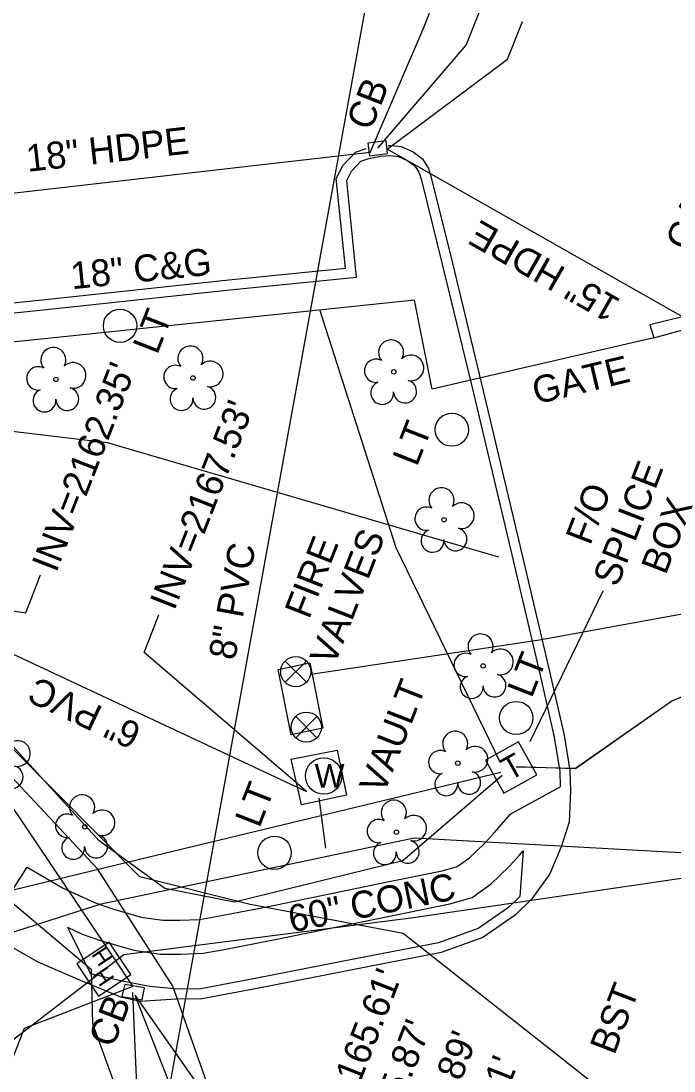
# Model space of a CAD drawing. Extents: x 945964 to 948456, y 631061 to 636061.
# Drawn here: x 946440.9 to 946537.5, y 633475.6 to 633631 of the extents above; entities that cross this region are included whole.
import ezdxf

# ---------------------------------------------------------------- set-up
doc = ezdxf.new("R2010")
doc.units = 0
for name, color, linetype in [('Exist Building', 7, 'Continuous'), ('Exist Building Text', 7, 'Continuous'), ('Exist Other Culture Fence Line', 7, 'Continuous'), ('Exist Other Culture Gate', 7, 'Continuous'), ('Exist Other Culture Gate Text', 7, 'Continuous'), ('Exist Roads Curbs', 7, 'Continuous'), ('Exist Roads Curbs Text', 7, 'Continuous'), ('Exist Roads EOP', 7, 'Continuous'), ('Exist Roads EOP Other', 7, 'Continuous'), ('Exist Roads EOP Other Text', 7, 'Continuous'), ('Exist Structure Minor Catch Basin', 7, 'Continuous'), ('Exist Structure Minor Catch Basin Text', 7, 'Continuous'), ('Exist Structure Minor Catch Basin Top Elevation', 7, 'Continuous'), ('Exist Structure Minor Pipes HDPE 15 Inch', 7, 'Continuous'), ('Exist Structure Minor Pipes HDPE 15 Inch Invert', 7, 'Continuous'), ('Exist Structure Minor Pipes HDPE 15 Inch Text', 7, 'Continuous'), ('Exist Structure Minor Pipes HDPE 18 Inch', 7, 'Continuous'), ('Exist Structure Minor Pipes HDPE 18 Inch Invert', 7, 'Continuous'), ('Exist Structure Minor Pipes HDPE 18 Inch Text', 7, 'Continuous'), ('Exist Structure Minor Pipes HDPE 8 Inch', 7, 'Continuous'), ('Exist Structure Minor Pipes HDPE 8 Inch Invert', 7, 'Continuous'), ('Exist Structure Minor Pipes HDPE 8 Inch Text', 7, 'Continuous'), ('Exist Structure Minor Pipes RCP 15 Inch Invert', 7, 'Continuous'), ('Exist Structure Minor Pipes RCP 18 Inch', 7, 'Continuous'), ('Exist Structure Minor Pipes RCP 18 Inch Invert', 7, 'Continuous'), ('Exist Utilities Gas UG Line SUE', 7, 'Continuous'), ('Exist Utilities Other Pole CELL', 7, 'Continuous'), ('Exist Utilities Other Pole Text', 7, 'Continuous'), ('Exist Utilities Power Hand Hole CELL', 7, 'Continuous'), ('Exist Utilities Power UG Cable SUE', 7, 'Continuous'), ('Exist Utilities Sanitary Sewer UG Line', 7, 'Continuous'), ('Exist Utilities Sanitary Sewer UG Line Text', 7, 'Continuous'), ('Exist Utilities Telephone Pedestal CELL', 7, 'Continuous'), ('Exist Utilities Telephone Pedestal Leader', 7, 'Continuous'), ('Exist Utilities Telephone Pedestal Text', 7, 'Continuous'), ('Exist Utilities Telephone UG Cable SUE', 7, 'Continuous'), ('Exist Utilities Telephone UG FO SUE', 7, 'Continuous'), ('Exist Utilities Water Manhole CELL', 7, 'Continuous'), ('Exist Utilities Water Manhole Text', 7, 'Continuous'), ('Exist Utilities Water UG Line SUE', 7, 'Continuous'), ('Exist Utilities Water Valve CELL', 7, 'Continuous'), ('Exist Utilities Water Valve Text', 7, 'Continuous'), ('Exist Vegetation Tree CELL', 7, 'Continuous')]:
    doc.layers.add(name, color=color, linetype=linetype)

# ---------------------------------------------------------------- blocks, each defined once
blk = doc.blocks.new('EXIST UTILITIES WATER VALVE')
at = {"layer": 'Exist Utilities Water Valve CELL'}
blk.add_lwpolyline([(0.0315, 0.0315), (-0.0315, -0.0315), (0, 0), (0.0315, -0.0315), (-0.0315, 0.0315)], dxfattribs=at)
blk.add_circle((0, 0), 0.0445, dxfattribs=at)
blk = doc.blocks.new('EXIST UTILITIES WATER MANHOLE')
at = {"layer": 'Exist Utilities Water Manhole CELL'}
blk.add_line((0, 0), (0, 0), dxfattribs=at)
blk.add_circle((0, 0.0001), 0.0539, dxfattribs=at)
blk.add_text('W', height=0.07, dxfattribs=at).set_placement((-0.027, -0.035))
blk = doc.blocks.new('EXIST UTILITIES POWER HAND HOLE')
at = {"layer": 'Exist Utilities Power Hand Hole CELL'}
blk.add_line((0, 0), (0, 0), dxfattribs=at)
blk.add_lwpolyline([(-0.059, -0.0545), (0.056, -0.0545), (0.056, 0.0605), (-0.059, 0.0605), (-0.059, -0.0545)], dxfattribs=at)
for p in [(-0.0432, -0.0095), (0.0081, -0.0399)]:
    blk.add_text('H', height=0.05, dxfattribs=at).set_placement(p)
blk = doc.blocks.new('EXIST UTILITIES TELEPHONE PEDESTAL')
at = {"layer": 'Exist Utilities Telephone Pedestal CELL'}
blk.add_line((0, 0), (0, 0), dxfattribs=at)
blk.add_lwpolyline([(-0.0545, -0.0565), (0.0574, -0.0565), (0.0574, 0.0554), (-0.0545, 0.0554), (-0.0545, -0.0565)], dxfattribs=at)
blk.add_text('T', height=0.0684, dxfattribs=at).set_placement((-0.0226, -0.0343))
blk = doc.blocks.new('EXIST UTILITIES OTHER POLE')
at = {"layer": 'Exist Utilities Other Pole CELL'}
blk.add_circle((0, 0), 0.0493, dxfattribs=at)
blk = doc.blocks.new('EXIST VEGETATION TREE')
at = {"layer": 'Exist Vegetation Tree CELL'}
blk.add_line((0, 0), (0, 0), dxfattribs=at)
blk.add_circle((0, 0), 0.00652, dxfattribs=at)
for centre, radius, start, end in [((-0.0077, 0.0575), 0.0371, 330.1651, 219.7134), ((-0.0521, 0.0031), 0.0345, 62.6636, 279.3457), ((0.051, 0.0118), 0.038, 257.1011, 134.1999), ((-0.0341, -0.0624), 0.0338, 111.5671, 6.231), ((0.0335, -0.058), 0.034, 181.2822, 74.56)]:
    blk.add_arc(centre, radius, start, end, dxfattribs=at)

msp = doc.modelspace()

# ---------------------------------------------------------------- linework, layer by layer
at = {"layer": 'Exist Building'}
msp.add_lwpolyline([(946543.38, 633588.34), (946533.92, 633586.01), (946534.53, 633584.13), (946543.64, 633586.62)], close=True, dxfattribs=at)
at = {"layer": 'Exist Other Culture Fence Line'}
msp.add_lwpolyline([(946509.53, 633578.35), (946501.69, 633576.5), (946499.1, 633589.68), (946405.09, 633579.86)], dxfattribs=at)
at = {"layer": 'Exist Other Culture Gate'}
msp.add_lwpolyline([(946534.53, 633584.13), (946509.53, 633578.35)], dxfattribs=at)
at = {"layer": 'Exist Roads Curbs'}
for points in [[(946417.48, 633585.5), (946445.09, 633588.36), (946471.78, 633591.22), (946490.51, 633593.1), (946489.07, 633607.4), (946489.76, 633608.79), (946491.18, 633610.27), (946492.34, 633610.67), (946494.05, 633611.01), (946495.56, 633611.08), (946496.71, 633610.95), (946498.12, 633610.33), (946499.15, 633609.56), (946499.81, 633608.55), (946500.13, 633607.44), (946503.25, 633594.82), (946507.82, 633575.9), (946512.9, 633554.49), (946517.62, 633534.38), (946519.78, 633525.01), (946520.6, 633519.9), (946520.66, 633517.66)], [(946514.7, 633501.41), (946513.02, 633499.79), (946508.53, 633496.67), (946502.64, 633494.55), (946490.38, 633492.18), (946475.77, 633489.3), (946467.24, 633487.69), (946463.6, 633487.75), (946459.94, 633488.06), (946455.83, 633488.89), (946451.17, 633489.94), (946451.06, 633490)]]:
    msp.add_lwpolyline(points, dxfattribs=at)
at = {"layer": 'Exist Roads EOP'}
for points in [[(946417.39, 633596.75), (946417.56, 633596.27), (946418.77, 633587.14), (946444.94, 633589.85), (946471.62, 633592.71), (946488.87, 633594.44), (946487.53, 633607.68), (946488.52, 633609.67), (946490.35, 633611.57), (946491.95, 633612.12)], [(946495.22, 633612.57), (946495.61, 633612.59), (946497.1, 633612.41), (946498.89, 633611.64), (946500.26, 633610.6), (946501.19, 633609.18), (946501.58, 633607.83), (946504.71, 633595.17), (946509.28, 633576.25), (946514.36, 633554.84), (946519.08, 633534.72), (946521.25, 633525.29), (946522.09, 633520.04), (946522.18, 633517.04), (946522, 633512.4), (946520.82, 633508.77), (946519.12, 633504.77), (946516.48, 633501.04), (946513.97, 633498.62), (946509.22, 633495.32), (946503.04, 633493.09), (946490.67, 633490.71), (946476.06, 633487.83), (946467.37, 633486.19), (946463.76, 633486.25)], [(946450.97, 633488.45), (946450.71, 633488.51), (946443.39, 633491.68), (946437.37, 633495.08), (946432.66, 633498.19), (946428.04, 633502.47), (946421.79, 633510.06), (946416.27, 633518.41), (946410.29, 633527.94), (946402.14, 633542.13), (946395.12, 633555.86)], [(946450.97, 633488.45), (946455.6, 633486.53), (946458.53, 633485.89), (946463.76, 633486.25)]]:
    msp.add_lwpolyline(points, dxfattribs=at)
at = {"layer": 'Exist Roads EOP Other'}
for points in [[(946485.55, 633526.32), (946480.87, 633525.33), (946478.9, 633535.01), (946483.62, 633535.98), (946485.55, 633526.32)], [(946487.67, 633523.08), (946489.01, 633516.41), (946482.39, 633514.97), (946480.85, 633521.73), (946487.67, 633523.08)], [(946441.79, 633505.74), (946447.12, 633502.62), (946451.76, 633500.5), (946454.28, 633499.62), (946458.63, 633498.35), (946461.87, 633497.89), (946464.37, 633497.89), (946467.29, 633498), (946470.01, 633498.47), (946477.27, 633499.87), (946494.87, 633503.51), (946503.17, 633505.19), (946505.42, 633505.83), (946507.25, 633507.14), (946508.21, 633508.05), (946509.55, 633509.35), (946510.89, 633510.85), (946513.34, 633513.62), (946520.66, 633517.66)], [(946447.73, 633496.84), (946449.9, 633495.85), (946452.76, 633494.85), (946457.57, 633493.46), (946461.52, 633492.89), (946464.47, 633492.89), (946467.82, 633493.02), (946470.91, 633493.56), (946478.25, 633494.97), (946495.88, 633498.61), (946504.35, 633500.33), (946507.62, 633501.26), (946510.44, 633503.28), (946511.68, 633504.45), (946513.16, 633505.88), (946514.63, 633507.53), (946515.18, 633508.15)], [(946515.18, 633508.15), (946514.7, 633501.41)], [(946439.19, 633501.66), (946441.79, 633505.74)], [(946447.73, 633496.84), (946451.17, 633489.94)], [(946450.97, 633488.45), (946455.6, 633486.53), (946458.53, 633485.89), (946463.76, 633486.25)]]:
    msp.add_lwpolyline(points, dxfattribs=at)
at = {"layer": 'Exist Structure Minor Catch Basin'}
for points in [[(946495.11, 633611.42), (946494.91, 633613.28), (946492.17, 633612.93), (946492.43, 633611.04), (946495.11, 633611.42)], [(946456.21, 633488.38), (946455.81, 633486.61), (946458.78, 633486.13), (946459.12, 633487.89), (946456.21, 633488.38)]]:
    msp.add_lwpolyline(points, dxfattribs=at)
at = {"layer": 'Exist Structure Minor Catch Basin Top Elevation'}
for points in [[(946493.66, 633612.2), (946506.75, 633627.44), (946508.94, 633633.03)], [(946457.36, 633487.17), (946458.13, 633470.03), (946455.94, 633464.44)]]:
    msp.add_lwpolyline(points, dxfattribs=at)
at = {"layer": 'Exist Structure Minor Pipes HDPE 15 Inch'}
msp.add_line((946603.38, 633550.42), (946495.07, 633612.05), dxfattribs=at)
at = {"layer": 'Exist Structure Minor Pipes HDPE 15 Inch Invert'}
msp.add_lwpolyline([(946495.07, 633612.05), (946512.88, 633625.34), (946515.06, 633630.92)], dxfattribs=at)
at = {"layer": 'Exist Structure Minor Pipes HDPE 18 Inch'}
msp.add_line((946492.54, 633611.54), (946411.45, 633602.28), dxfattribs=at)
at = {"layer": 'Exist Structure Minor Pipes HDPE 18 Inch Invert'}
msp.add_lwpolyline([(946492.54, 633611.54), (946500.47, 633630.05), (946502.66, 633635.64)], dxfattribs=at)
at = {"layer": 'Exist Structure Minor Pipes HDPE 8 Inch'}
msp.add_lwpolyline([(946419.33, 633546.79), (946483.14, 633516.94)], dxfattribs=at)
at = {"layer": 'Exist Structure Minor Pipes HDPE 8 Inch Invert'}
for points in [[(946419.33, 633546.79), (946441.57, 633543.41), (946443.76, 633549)], [(946483.14, 633516.94), (946459.07, 633537.52), (946461.26, 633543.11)]]:
    msp.add_lwpolyline(points, dxfattribs=at)
at = {"layer": 'Exist Structure Minor Pipes RCP 18 Inch'}
for p, q in [((946418.32, 633546.11), (946457.44, 633488.09)), ((946457.69, 633486.78), (946475.14, 633442.57))]:
    msp.add_line(p, q, dxfattribs=at)
at = {"layer": 'Exist Structure Minor Pipes RCP 18 Inch Invert'}
for points in [[(946457.44, 633488.09), (946441.35, 633481.87), (946439.16, 633476.28)], [(946457.69, 633486.78), (946481.4, 633453.03), (946483.58, 633458.62)]]:
    msp.add_lwpolyline(points, dxfattribs=at)
at = {"layer": 'Exist Utilities Gas UG Line SUE'}
msp.add_lwpolyline([(946411.39, 633466.47), (946436.6, 633477.85), (946456.09, 633492.82), (946498.96, 633498.31), (946548.31, 633505.55), (946613.29, 633503.43), (946703.83, 633469.18), (946794.76, 633441.92), (946806, 633432.1), (946821.36, 633424.58)], dxfattribs=at)
at = {"layer": 'Exist Utilities Power UG Cable SUE'}
for points in [[(946635.14, 632865.8), (946629.47, 632896.55), (946595.83, 632887.24), (946588.05, 632902.07), (946565.48, 632967.5), (946565.84, 632977.61), (946565.32, 632980.27), (946555.6, 632997.55), (946522.14, 633095.32), (946521.35, 633107.95), (946521.64, 633110.72), (946553.29, 633127.22), (946568.2, 633134.98), (946566.11, 633154.95), (946530.06, 633261.25), (946518.07, 633301.87), (946482.92, 633416.06), (946475.99, 633414.94), (946451.49, 633482.54), (946451.32, 633490.54), (946420.98, 633516.12), (946400.78, 633553.04), (946391.57, 633575.17)], [(946485.31, 633431.45), (946479.38, 633442.7), (946463.36, 633488.11), (946452.17, 633505.48), (946414.56, 633545.7), (946349.36, 633554.61), (946345.45, 633551.29), (946346.17, 633537.3)]]:
    msp.add_lwpolyline(points, dxfattribs=at)
at = {"layer": 'Exist Utilities Sanitary Sewer UG Line'}
msp.add_lwpolyline([(946508.67, 633725.95), (946453.33, 633420.85)], dxfattribs=at)
at = {"layer": 'Exist Utilities Telephone Pedestal Leader'}
msp.add_lwpolyline([(946516.23, 633524.36), (946527, 633546.64)], dxfattribs=at)
at = {"layer": 'Exist Utilities Telephone UG Cable SUE'}
for points in [[(946514.14, 633520.65), (946522.93, 633520.36), (946537.18, 633530.38), (946615.16, 633562.19), (946622.05, 633569.97)], [(946536.65, 633464.99), (946497.43, 633495.95), (946474.76, 633500.23), (946458.43, 633504.32), (946433.69, 633529.22), (946416.86, 633554.75)], [(946512.09, 633519.34), (946497.36, 633506.69), (946472.45, 633500.56), (946462.15, 633502.59), (946452.45, 633509.66), (946425.2, 633539.45), (946417.63, 633555.44)]]:
    msp.add_lwpolyline(points, dxfattribs=at)
at = {"layer": 'Exist Utilities Telephone UG FO SUE'}
for points in [[(946511.83, 633521.19), (946496.36, 633553.02), (946485.16, 633588.1)], [(946409.38, 633568.26), (946439.16, 633570.35), (946453.63, 633568.59), (946511.54, 633551.68)], [(946514.15, 633520.6), (946522.9, 633520.38), (946537.19, 633530.37), (946615.2, 633562.29), (946622.1, 633569.99)], [(946511.86, 633519.77), (946458.01, 633506.76), (946401.41, 633493.07), (946376.47, 633487.92)]]:
    msp.add_lwpolyline(points, dxfattribs=at)
at = {"layer": 'Exist Utilities Water UG Line SUE'}
msp.add_line((946484.92, 633516), (946485.93, 633508.56), dxfattribs=at)
for points in [[(946483.75, 633534.3), (946517.58, 633539.38), (946574.7, 633549.82), (946641.63, 633563.79)], [(946472.57, 633239.55), (946443.99, 633324.66), (946419.97, 633402.56), (946404.47, 633448.42), (946393.04, 633481.21), (946452.73, 633500.32), (946499.06, 633510.07), (946542.99, 633507.65), (946602.6, 633496.16), (946703.36, 633462.75), (946774.9, 633437.64), (946828.32, 633438.65), (946848.97, 633454.44)]]:
    msp.add_lwpolyline(points, dxfattribs=at)

# ---------------------------------------------------------------- block references
at = {"layer": 'Exist Utilities Other Pole CELL', "xscale": 50, "yscale": 50}
for p in [(946455.52, 633585.89), (946504.62, 633570.51), (946514.16, 633527.83), (946478.39, 633507.88)]:
    msp.add_blockref('EXIST UTILITIES OTHER POLE', p, dxfattribs=at)
at = {"layer": 'Exist Utilities Power Hand Hole CELL', "xscale": 49.999999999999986, "yscale": 49.999999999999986, "rotation": 123.86249742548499}
msp.add_blockref('EXIST UTILITIES POWER HAND HOLE', (946453.19, 633490.78), dxfattribs=at)
at = {"layer": 'Exist Utilities Telephone Pedestal CELL', "xscale": 49.999999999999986, "yscale": 49.99999999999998, "rotation": 29.237723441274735}
msp.add_blockref('EXIST UTILITIES TELEPHONE PEDESTAL', (946513.32, 633520.5), dxfattribs=at)
at = {"layer": 'Exist Utilities Water Manhole CELL', "xscale": 50, "yscale": 50}
msp.add_blockref('EXIST UTILITIES WATER MANHOLE', (946485.67, 633519.25), dxfattribs=at)
at = {"layer": 'Exist Utilities Water Valve CELL', "xscale": 50, "yscale": 50}
for p in [(946481.52, 633534.69), (946483.09, 633526.48)]:
    msp.add_blockref('EXIST UTILITIES WATER VALVE', p, dxfattribs=at)
at = {"layer": 'Exist Vegetation Tree CELL', "xscale": 50, "yscale": 50}
for p in [(946496.02, 633579.07), (946446.04, 633577.95), (946466.32, 633578.16), (946503.48, 633557.18), (946509.26, 633535.54), (946437.8, 633521.98), (946505.51, 633521.14), (946450.3, 633511.72), (946496.42, 633510.93)]:
    msp.add_blockref('EXIST VEGETATION TREE', p, dxfattribs=at)

# ---------------------------------------------------------------- texts
at = {"layer": 'Exist Building Text'}
msp.add_text('GATE CONTROL BOX', height=4, rotation=68.619, dxfattribs=at).set_placement((946539.86, 633596.76))
at = {"layer": 'Exist Other Culture Gate Text'}
msp.add_text('GATE', height=4, rotation=13.5878, dxfattribs=at).set_placement((946517.09, 633574.24))
at = {"layer": 'Exist Roads Curbs Text'}
msp.add_text('18" C&G', height=4, rotation=5.9757, dxfattribs=at).set_placement((946448.42, 633591.29))
at = {"layer": 'Exist Roads EOP Other Text'}
for s, rotation, p in [('60" CONC', 11.4908, (946480.88, 633496.05)), ('BST', 68.935, (946528.67, 633477.81))]:
    msp.add_text(s, height=4, rotation=rotation, dxfattribs=at).set_placement(p)
at = {"layer": 'Exist Structure Minor Catch Basin Text'}
for rotation, p in [(68.4718, (946492.64, 633614.61)), (68.619, (946454.48, 633478.85))]:
    msp.add_text('CB', height=4, rotation=rotation, dxfattribs=at).set_placement(p)
at = {"layer": 'Exist Structure Minor Catch Basin Top Elevation'}
msp.add_text("TOP=2168.89'", height=4, rotation=68.6189, dxfattribs=at).set_placement((946495.93, 633448.32))
at = {"layer": 'Exist Structure Minor Pipes HDPE 15 Inch Text'}
msp.add_text('15" HDPE', height=4, rotation=150.3616, dxfattribs=at).set_placement((946529.8, 633589.7))
at = {"layer": 'Exist Structure Minor Pipes HDPE 18 Inch Text'}
msp.add_text('18" HDPE', height=4, rotation=6.5114, dxfattribs=at).set_placement((946441.85, 633608.67))
at = {"layer": 'Exist Structure Minor Pipes HDPE 8 Inch Invert'}
for s, p in [("INV=2162.35'", (946446.08, 633549.22)), ("INV=2167.53'", (946463.55, 633543.61))]:
    msp.add_text(s, height=4, rotation=68.6189, dxfattribs=at).set_placement(p)
at = {"layer": 'Exist Structure Minor Pipes HDPE 8 Inch Text'}
msp.add_text('6" PVC', height=4, rotation=154.9304, dxfattribs=at).set_placement((946458.95, 633526.68))
at = {"layer": 'Exist Structure Minor Pipes RCP 15 Inch Invert'}
msp.add_text("INV=2165.81'", height=4, rotation=68.6189, dxfattribs=at).set_placement((946502.72, 633446.57))
at = {"layer": 'Exist Structure Minor Pipes RCP 18 Inch Invert'}
for s, p in [("INV=2165.61'", (946485.49, 633459.5)), ("INV=2165.87'", (946489.83, 633451.94))]:
    msp.add_text(s, height=4, rotation=68.6189, dxfattribs=at).set_placement(p)
at = {"layer": 'Exist Utilities Other Pole Text'}
for p in [(946461.02, 633581.48), (946499.45, 633564.91), (946516.43, 633530.63), (946476.14, 633511.42)]:
    msp.add_text('LT', height=4, rotation=68.619, dxfattribs=at).set_placement(p)
at = {"layer": 'Exist Utilities Sanitary Sewer UG Line Text'}
msp.add_text('8" PVC', height=4, rotation=79.7192, dxfattribs=at).set_placement((946472.53, 633536.25))
at = {"layer": 'Exist Utilities Telephone Pedestal Text'}
for s, p in [('SPLICE', (946529.13, 633547.07)), ('F/O', (946525.08, 633553.25)), ('BOX', (946536.26, 633548.87))]:
    msp.add_text(s, height=4, rotation=68.8493, dxfattribs=at).set_placement(p)
at = {"layer": 'Exist Utilities Water Manhole Text'}
msp.add_text('VAULT', height=4, rotation=68.619, dxfattribs=at).set_placement((946494.55, 633516.39))
at = {"layer": 'Exist Utilities Water Valve Text'}
for s, p in [('VALVES', (946487.22, 633535.39)), ('FIRE', (946483.49, 633542.33))]:
    msp.add_text(s, height=4, rotation=68.619, dxfattribs=at).set_placement(p)

doc.saveas('drawing.dxf')
